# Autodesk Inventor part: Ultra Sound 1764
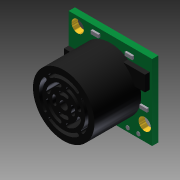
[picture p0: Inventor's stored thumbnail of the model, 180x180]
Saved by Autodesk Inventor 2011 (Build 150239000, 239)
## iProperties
Created: 2011-02
Part Number: Ultra Sound 1764
Document SubType Name: Modeling
Designer: asheafer
Density: 1 g/cm^3
Author: asheafer
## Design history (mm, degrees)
sketch "Sketch1"
  geometry: L1 (-25.524, 12.727)-(-3.299, 12.727); L2 (-3.299, 12.727)-(-3.299, -7.339); L3 (-3.299, -7.339)-(-25.524, -7.339); L4 (-25.524, -7.339)-(-25.524, 12.727)
  constraints: 8 end point, 2 parallel, 1 horizontal, 1 perpendicular
  dimensions: "d1" = 22.225 distance of L1.start L1.end; "d2" = 20.066 distance of L1.end L2.end
extrude "Extrusion1" new body sketch "Sketch1" distance "d3" = 1.651; taper "d4" = 0 deg
sketch "Sketch2"
  geometry: C1 r 8.192 at (-14.412, 2.694); 1 further point
  constraints: 1 centre point
  dimensions: "d5" = 16.383 diameter of C1
extrude "Extrusion2" join sketch "Sketch2" distance "d6" = 12.446; taper "d7" = 0 deg
sketch "Sketch3"
  geometry: L1 (-3.299, 12.727)-(-3.299, -7.339) reference; L2 (-25.524, 12.727)-(-3.299, 12.727) reference; L3 (-25.524, -7.339)-(-25.524, 12.727) reference; L4 (-3.299, -7.339)-(-25.524, -7.339) reference; A1 r 1.651 centre (-23.129, 10.38) between (-23.591, 11.965) and (-24.762, 10.621); A2 r 1.651 centre (-5.265, -3.268) between (-5.882, -4.799) and (-4.061, -4.398); 1 further point
  constraints: 4 point on circle, 2 centre point
  dimensions: "d8" = 3.302 diameter of A1; "d9" = 0.762 distance from line of L2 A1.start; "d10" = 0.762 distance from line of L3 A1.end; "d11" = 3.302 diameter of A2; "d12" = 0.762 distance from line of L1 A2.end; "d13" = 2.54 distance from line of L4 A2.start
extrude "Extrusion3" cut sketch "Sketch3" stored distance "d14" = 12.446; taper "d15" = 0 deg
sketch "Sketch4"
  geometry: L1 (-0.811, 2.442)-(0.81, 2.442); C1 r 8.192 at (0, 0) reference; C2 r 1.08 at (0, 0); A1 r 0.477 centre (-0.811, 2.442) between (-0.912, 2.908) and (-0.66, 1.989); A2 r 0.477 centre (0.81, 2.442) between (0.66, 1.989) and (0.92, 2.906); A3 r 0.477 centre (-2.442, -0.811) between (-2.908, -0.912) and (-1.989, -0.66); A4 r 0.477 centre (-2.442, 0.81) between (-1.989, 0.66) and (-2.906, 0.92); A5 r 0.477 centre (0.811, -2.442) between (0.912, -2.908) and (0.66, -1.989); A6 r 0.477 centre (-0.81, -2.442) between (-0.66, -1.989) and (-0.92, -2.906); A7 r 0.477 centre (2.442, 0.811) between (2.908, 0.912) and (1.989, 0.66); A8 r 0.477 centre (2.442, -0.81) between (1.989, -0.66) and (2.906, -0.92); A9 r 2.096 centre (0, 0) between (0.66, 1.989) and (-0.66, 1.989); A10 r 3.048 centre (0, 0) between (0.999, 2.88) and (-1.009, 2.876); A11 r 3.048 centre (0, 0) between (2.88, -0.999) and (2.876, 1.009); A12 r 2.096 centre (0, 0) between (1.989, -0.66) and (1.989, 0.66); A13 r 2.096 centre (0, 0) between (-1.989, 0.66) and (-1.989, -0.66); A14 r 2.096 centre (0, 0) between (-0.66, -1.989) and (0.66, -1.989); A15 r 3.048 centre (0, 0) between (-2.88, 0.999) and (-2.876, -1.009); A16 r 3.048 centre (0, 0) between (-0.999, -2.88) and (1.009, -2.876); A17 r 0.476 centre (-1.052, 4.155) between (-0.935, 3.693) and (-1.169, 4.617); A18 r 0.476 centre (-4.155, 1.052) between (-4.617, 1.169) and (-3.693, 0.935); A19 r 0.476 centre (-4.155, -1.052) between (-3.693, -0.935) and (-4.617, -1.169); A20 r 0.476 centre (-1.052, -4.155) between (-1.169, -4.617) and (-0.935, -3.693); A21 r 0.476 centre (1.052, -4.155) between (0.935, -3.693) and (1.169, -4.617); A22 r 0.476 centre (4.155, -1.052) between (4.617, -1.169) and (3.693, -0.935); A23 r 0.476 centre (4.155, 1.052) between (3.693, 0.935) and (4.617, 1.169); A24 r 0.476 centre (1.052, 4.155) between (1.169, 4.617) and (0.935, 3.693); A25 r 4.763 centre (0, 0) between (-4.617, -1.169) and (-1.169, -4.617); A26 r 3.81 centre (0, 0) between (-3.693, -0.935) and (-0.935, -3.693); A27 r 4.763 centre (0, 0) between (1.169, -4.617) and (4.617, -1.169); A28 r 3.81 centre (0, 0) between (0.935, -3.693) and (3.693, -0.935); A29 r 3.81 centre (0, 0) between (3.693, 0.935) and (0.935, 3.693); A30 r 3.81 centre (0, 0) between (-0.935, 3.693) and (-3.693, 0.935); A31 r 4.763 centre (0, 0) between (4.617, 1.169) and (1.169, 4.617); A32 r 4.763 centre (0, 0) between (-1.169, 4.617) and (-4.617, 1.169); A33 r 0.447 centre (-3.597, 5.004) between (-3.915, 5.319) and (-3.336, 4.641); A34 r 0.447 centre (3.597, 5.004) between (3.336, 4.641) and (3.915, 5.319); A35 r 0.447 centre (-5.004, -3.597) between (-5.319, -3.915) and (-4.641, -3.336); A36 r 0.447 centre (-5.004, 3.597) between (-4.641, 3.336) and (-5.319, 3.915); A37 r 0.447 centre (3.597, -5.004) between (3.915, -5.319) and (3.336, -4.641); A38 r 0.447 centre (-3.597, -5.004) between (-3.336, -4.641) and (-3.915, -5.319); A39 r 0.447 centre (5.004, 3.597) between (5.319, 3.915) and (4.641, 3.336); A40 r 0.447 centre (5.004, -3.597) between (4.641, -3.336) and (5.319, -3.915); A41 r 6.604 centre (0, 0) between (5.319, -3.915) and (5.319, 3.915); A42 r 5.715 centre (0, 0) between (4.641, -3.336) and (4.641, 3.336); A43 r 6.604 centre (0, 0) between (-3.915, -5.319) and (3.915, -5.319); A44 r 5.715 centre (0, 0) between (-3.336, -4.641) and (3.336, -4.641); A45 r 5.715 centre (0, 0) between (3.336, 4.641) and (-3.336, 4.641); A46 r 5.715 centre (0, 0) between (-4.641, 3.336) and (-4.641, -3.336); A47 r 6.604 centre (0, 0) between (3.915, 5.319) and (-3.915, 5.319); A48 r 6.604 centre (0, 0) between (-5.319, 3.915) and (-5.319, -3.915); 25 further points
  constraints: 112 point on circle, 49 centre point, 7 coincident, 2 end point, 2 equal radius, 1 horizontal, 123 other
  dimensions: "d16" = 2.159 diameter of C2; "d22" = 360 deg dimension on C1.centre L1.start (derived); "d30" = 360 deg dimension on C1.centre A17.centre (derived); "d35" = 7.874 distance of point (3.937, 4.713) point (-3.937, 4.713); "d38" = 360 deg dimension on C1.centre A33.centre (derived)
extrude "Extrusion4" cut sketch "Sketch4" distance "d40" = 6.35; taper "d41" = 0 deg
sketch "Sketch5"
  geometry: L1 (-25.524, 12.727)-(-3.299, 12.727) reference; L2 (-25.524, -7.339)-(-25.524, 12.727) reference; L3 (-3.299, -7.339)-(-25.524, -7.339) reference; L4 (-25.524, 0.662)-(-22.347, 0.662); L5 (-22.347, 0.662)-(-22.347, 4.726); L6 (-22.347, 4.726)-(-25.524, 4.726); L7 (-25.524, 4.726)-(-25.524, 0.662); L8 (-3.299, 12.727)-(-3.299, -7.339) reference; L9 (-9.744, 9.425)-(-3.934, 9.425); L10 (-3.934, 9.425)-(-3.934, 5.35); L11 (-3.934, 5.35)-(-9.744, 5.35); L12 (-9.744, 5.35)-(-9.744, 9.425); A1 r 8.192 centre (-14.412, 2.694) between (-22.347, 4.726) and (-9.744, 9.425) reference; 1 further point
  constraints: 16 end point, 4 parallel, 2 horizontal, 2 perpendicular, 2 point on circle, 1 point on line
  dimensions: "d42" = 8.001 distance between parallel lines of L1 L6; "d43" = 8.001 distance between parallel lines of L3 L4; "d54" = 4.07479 distance of L9.end L10.end; "d55" = 3.302 distance between parallel lines of L1 L9; "d56" = 0.635 distance between parallel lines of L8 L10
extrude "Extrusion5" join sketch "Sketch5" distance "d44" = 1.27; taper "d45" = 0 deg
sketch "Sketch7"
  geometry: L1 (1.651, 12.065)-(2.921, 12.065); L2 (2.921, 12.065)-(2.921, 8.001); L3 (2.921, 8.001)-(1.651, 8.001); L4 (1.651, 8.001)-(1.651, 12.065); 1 further point
  constraints: 8 end point, 2 parallel, 1 horizontal, 1 perpendicular
extrude "Extrusion8" join sketch "Sketch7" distance "d52" = 0.00003; taper "d53" = 0 deg
extrude "Extrusion9" join sketch "Sketch5" distance "d57" = 1.27; taper "d58" = 0 deg
sketch "Sketch8"
  geometry: L1 (-25.524, -7.339)-(-25.524, 0.662) reference; L2 (-3.299, -7.339)-(-25.524, -7.339) reference; L3 (-24.508, -6.323)-(-25.016, -6.323); L4 (-24.508, -6.831)-(-24.508, -6.323); C1 r 0.508 at (-21.478, -6.323); C2 r 0.508 at (-18.369, -6.323); C3 r 0.508 at (-15.58, -6.323); C4 r 0.508 at (-12.791, -6.323); C5 r 0.508 at (-9.744, -6.323); C6 r 0.508 at (-6.916, -6.323); A1 r 0.508 centre (-24.508, -6.323) between (-25.016, -6.323) and (-24.508, -6.831); 1 further point
  constraints: 7 centre point, 4 end point, 2 point on circle, 1 horizontal, 1 vertical
  dimensions: "d59" = 1.016 diameter of A1; "d62" = 0.508 distance from line of L1 L3.end; "d63" = 0.508 distance from line of L2 L4.start; "d64" = 1.016 diameter of C1; "d65" = 1.016 diameter of C2; "d66" = 1.016 diameter of C3; "d67" = 1.016 diameter of C4; "d68" = 1.016 diameter of C5; "d69" = 1.016 diameter of C6
extrude "Extrusion10" cut sketch "Sketch8" stored distance "d70" = 1.27; taper "d71" = 0 deg
extrude "Extrusion11" join sketch "Sketch8" distance "d72" = 0.127; taper "d73" = 0 deg
sketch "Sketch9"
  geometry: L1 (-25.004, -0.689)-(-22.972, -0.689); L2 (-22.972, -0.689)-(-22.972, -1.578); L3 (-22.972, -1.578)-(-25.004, -1.578); L4 (-25.004, -1.578)-(-25.004, -0.689); L5 (-22.08, -2.777)-(-24.112, -2.777); L6 (-24.112, -1.888)-(-22.08, -1.888); L7 (-22.08, -1.888)-(-22.08, -2.777); L8 (-24.112, -2.777)-(-24.112, -1.888); L9 (-4.178, 0.154)-(-6.21, 0.154); L10 (-6.21, 1.043)-(-4.178, 1.043); L11 (-4.178, 1.043)-(-4.178, 0.154); L12 (-6.21, 0.154)-(-6.21, 1.043); L13 (-4.472, 10.87)-(-6.504, 10.87); L14 (-6.504, 11.759)-(-4.472, 11.759); L15 (-4.472, 11.759)-(-4.472, 10.87); L16 (-6.504, 10.87)-(-6.504, 11.759); L17 (-8.1, 10.32)-(-10.132, 10.32); L18 (-10.132, 11.209)-(-8.1, 11.209); L19 (-8.1, 11.209)-(-8.1, 10.32); L20 (-10.132, 10.32)-(-10.132, 11.209); L21 (-17.138, 10.81)-(-19.17, 10.81); L22 (-19.17, 11.699)-(-17.138, 11.699); L23 (-17.138, 11.699)-(-17.138, 10.81); L24 (-19.17, 10.81)-(-19.17, 11.699); 1 further point
  constraints: 48 end point, 12 parallel, 6 horizontal, 6 perpendicular
  dimensions: "d74" = 2.032 distance of L2.end L3.end; "d75" = 0.889 distance of L3.end L1.start; "d76" = 2.032 distance of L5.start L5.end; "d77" = 0.889 distance of L5.end L6.start; "d78" = 2.032 distance of L9.start L9.end; "d79" = 0.889 distance of L9.end L10.start; "d80" = 2.032 distance of L13.start L13.end; "d81" = 0.889 distance of L13.end L14.start; "d82" = 2.032 distance of L17.start L17.end; "d83" = 0.889 distance of L17.end L18.start; "d84" = 2.032 distance of L21.start L21.end; "d85" = 0.889 distance of L21.end L22.start
extrude "Extrusion12" join sketch "Sketch9" distance "d86" = 0.508; taper "d87" = 0 deg
body "Solid1"
other parameters: "d17" = 4.191, "d18" = 6.096, "d24" = 7.62, "d25" = 9.525, "d32" = 11.43, "d33" = 13.208
